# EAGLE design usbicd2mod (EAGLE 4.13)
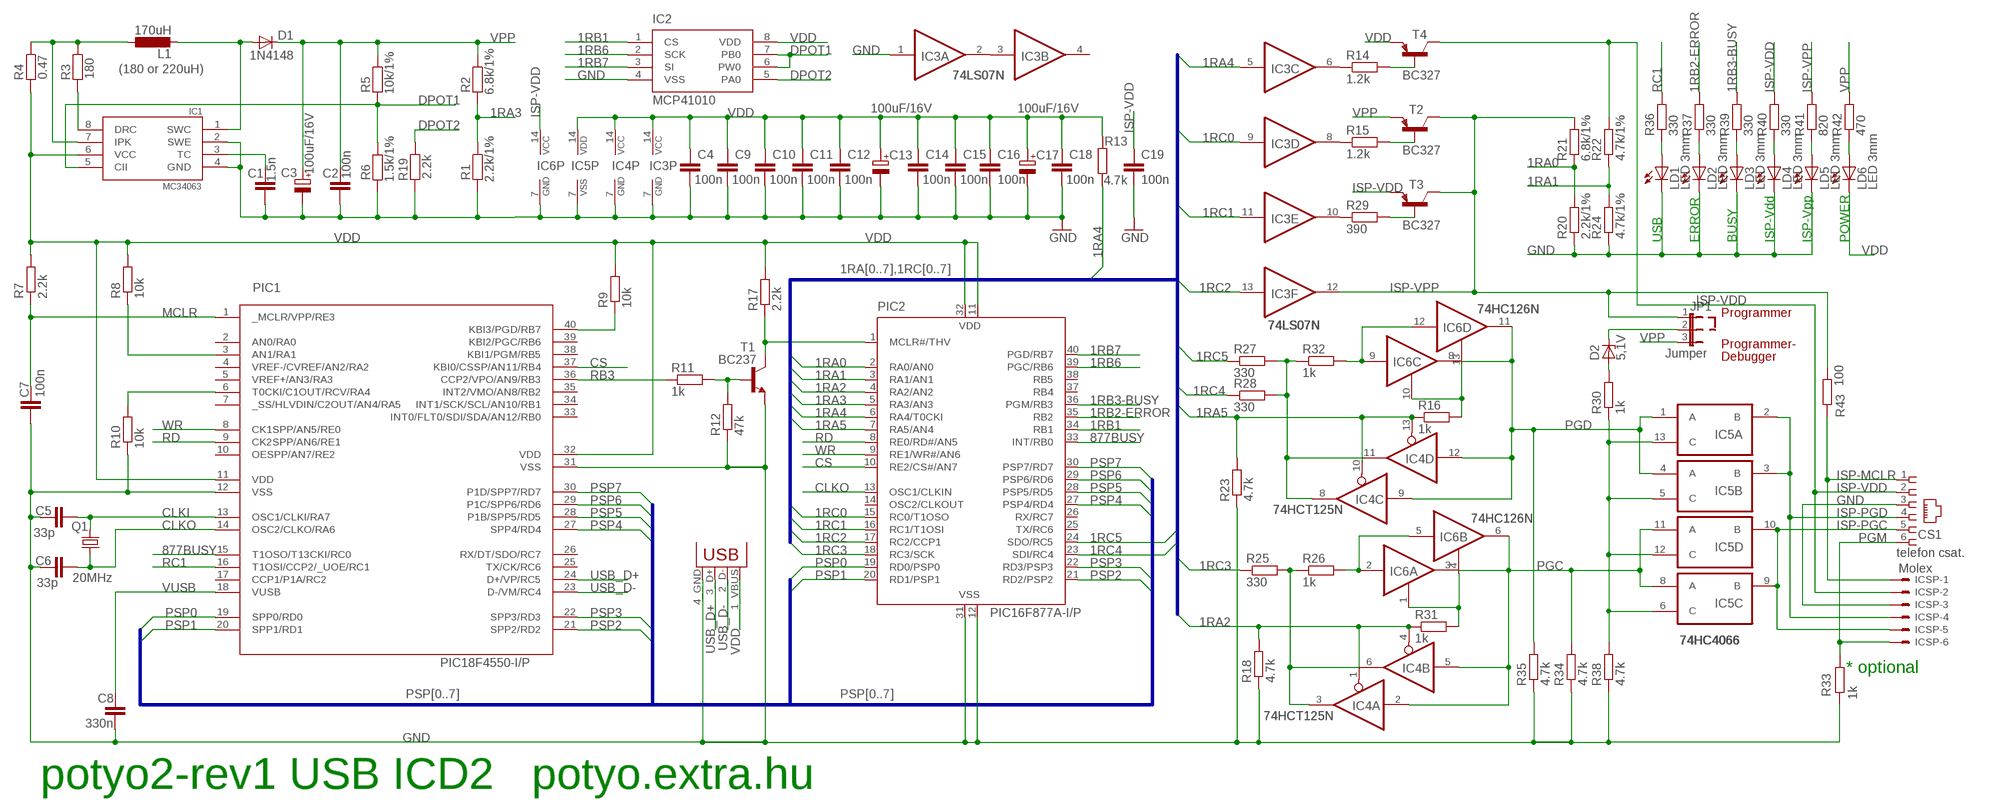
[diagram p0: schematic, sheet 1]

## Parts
C1  1.5n  C-EU025-025X050  [C025-025X050]
C2  100n  C-EU025-024X044  [C025-024X044]
C3  100uF/16V  CPOL-EUE2.5-5  [E2,5-5]
C4  100n  C-EU025-024X044  [C025-024X044]
C5  33p  C-EU025-024X044  [C025-024X044]
C6  33p  C-EU025-024X044  [C025-024X044]
C7  100n  C-EU025-024X044  [C025-024X044]
C8  330n  C-EU050-035X075  [C050-035X075]
C9  100n  C-EU025-024X044  [C025-024X044]
C10  100n  C-EU025-024X044  [C025-024X044]
C11  100n  C-EU025-024X044  [C025-024X044]
C12  100n  C-EU025-024X044  [C025-024X044]
C13  100uF/16V  CPOL-EUE2.5-5  [E2,5-5]
C14  100n  C-EU025-024X044  [C025-024X044]
C15  100n  C-EU025-024X044  [C025-024X044]
C16  100n  C-EU025-024X044  [C025-024X044]
C17  100uF/16V  CPOL-EUE2.5-5  [E2,5-5]
C18  100n  C-EU025-024X044  [C025-024X044]
C19  100n  C-EU025-024X044  [C025-024X044]
CS1  telefon csat.  520470-3  [520470-3]
D1  1N4148  1N414834-5  [DO34-5]
D2  5,1V  ZENER-DIODEDO34-5  [DO34Z5]
IC1  MC34063  MC34063-DIL  [DIL08]
IC2  MCP41010  [DIL8]
IC3  74LS07N  [DIL14]
IC4  74HCT125N  74HC125N  [DIL14]
IC5  74HC4066  4066N  [DIL14]
IC6  74HC126N  [DIL14]
ICSP  Molex  22-05-7068-06  [7395-06]
JP1  Jumper  JP2E  [JP2]
L1  170uH  L-EUL2207VM  [L2207VM]
LD1  LED 3mm  LED3MM  [LED3MM]
LD2  LED 3mm  LED3MM  [LED3MM]
LD3  LED 3mm  LED3MM  [LED3MM]
LD4  LED 3mm  LED3MM  [LED3MM]
LD5  LED 3mm  LED3MM  [LED3MM]
LD6  LED 3mm  LED3MM  [LED3MM]
PIC1  PIC18F4550-I/P  [DIL40]
PIC2  PIC16F877A-I/P  PIC16F877P  [DIL40]
Q1  20MHz  CRYTALHC49U-V  [HC49U-V]
R1  2.2k/1%  R-EU_0204/5  [0204/5@1]
R2  6.8k/1%  R-EU_0204/5  [0204/5@1]
R3  180  R-EU_0204/5  [0204/5@1]
R4  0.47  R-EU_0204/5  [0204/5@1]
R5  10k/1%  R-EU_0204/5  [0204/5@1]
R6  1.5k/1%  R-EU_0204/5  [0204/5@1]
R7  2.2k  R-EU_0204/5  [0204/5@1]
R8  10k  R-EU_0204/5  [0204/5@1]
R9  10k  R-EU_0204/5  [0204/5@1]
R10  10k  R-EU_0204/5  [0204/5@1]
R11  1k  R-EU_0204/5  [0204/5@1]
R12  47k  R-EU_0204/5  [0204/5@1]
R13  4.7k  R-EU_0204/5  [0204/5@1]
R14  1.2k  R-EU_0204/5  [0204/5@1]
R15  1.2k  R-EU_0204/5  [0204/5@1]
R16  1k  R-EU_0204/5  [0204/5@1]
R17  2.2k  R-EU_0204/5  [0204/5@1]
R18  4.7k  R-EU_0204/5  [0204/5@1]
R19  2.2k  R-EU_0204/5  [0204/5@1]
R20  2.2k/1%  R-EU_0204/5  [0204/5@1]
R21  6.8k/1%  R-EU_0204/5  [0204/5@1]
R22  4.7k/1%  R-EU_0204/5  [0204/5@1]
R23  4.7k  R-EU_0204/5  [0204/5@1]
R24  4.7k/1%  R-EU_0204/5  [0204/5@1]
R25  330  R-EU_0204/5  [0204/5@1]
R26  1k  R-EU_0204/5  [0204/5@1]
R27  330  R-EU_0204/5  [0204/5@1]
R28  330  R-EU_0204/5  [0204/5@1]
R29  390  R-EU_0204/5  [0204/5@1]
R30  1k  R-EU_0204/5  [0204/5@1]
R31  1k  R-EU_0204/5  [0204/5@1]
R32  1k  R-EU_0204/5  [0204/5@1]
R33  1k  R-EU_0204/5  [0204/5@1]
R34  4.7k  R-EU_0204/5  [0204/5@1]
R35  4.7k  R-EU_0204/5  [0204/5@1]
R36  330  R-EU_0204/5  [0204/5@1]
R37  330  R-EU_0204/5  [0204/5@1]
R38  4.7k  R-EU_0204/5  [0204/5@1]
R39  330  R-EU_0204/5  [0204/5@1]
R40  330  R-EU_0204/5  [0204/5@1]
R41  820  R-EU_0204/5  [0204/5@1]
R42  470  R-EU_0204/5  [0204/5@1]
R43  100  R-EU_0204/5  [0204/5@1]
T1  BC237  [TO92]
T2  BC327  [TO92]
T3  BC327  [TO92]
T4  BC327  [TO92]
USB  USB-B-H  [USB-B-H]

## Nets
1RA0: PIC2.2(RA0/AN0) R20.2 R21.1
1RA1: PIC2.3(RA1/AN1) R22.1 R24.2
1RA2: IC4.1(A:OE) IC4.4(B:OE) PIC2.4(RA2/AN2) R18.2 R31.1
1RA3: PIC2.5(RA3/AN3) R1.1 R2.2
1RA4: IC3.5(C:I) PIC2.6(RA4/T0CKI) R13.1
1RA5: IC4.10(C:OE) IC4.13(D:OE) PIC2.7(RA5/AN4) R16.1 R23.2
1RB1: IC2.1(CS) PIC2.34(RB1)
1RB2-ERROR: PIC2.35(RB2) R37.2
1RB3-BUSY: PIC2.36(PGM/RB3) R39.2
1RB6: IC2.2(SCK) PIC2.39(PGC/RB6)
1RB7: IC2.3(SI) PIC2.40(PGD/RB7)
1RC0: IC3.9(D:I) PIC2.15(RC0/T1OSO)
1RC1: IC3.11(E:I) PIC2.16(RC1/T1OSI)
1RC2: IC3.13(F:I) PIC2.17(RC2/CCP1)
1RC3: PIC2.18(RC3/SCK) R25.1
1RC4: PIC2.23(SDI/RC4) R28.1
1RC5: PIC2.24(SDO/RC5) R27.1
877BUSY: PIC1.15(T1OSO/T13CKI/RC0) PIC2.33(INT/RB0)
CLKI: C5.2 PIC1.13(OSC1/CLKI/RA7) Q1.2
CLKO: C6.2 PIC1.14(OSC2/CLKO/RA6) PIC2.13(OSC1/CLKIN) Q1.1
CMOS-EN: IC5.5(B:C) IC5.6(C:C) IC5.12(D:C) IC5.13(A:C) R30.1 R38.2
CS: PIC1.37(KBI0/CSSP/AN11/RB4) PIC2.10(RE2/CS#/AN7)
DPOT1: IC1.5(CII) IC2.6(PW0) IC2.7(PB0) R5.2 R6.2
DPOT2: IC2.5(PA0) R19.1
GND: C1.2 C2.2 C3.- C4.2 C5.1 C6.1 C7.2 C8.2 C9.2 C10.2 C11.2 C12.2 C13.- C14.2 C15.2 C16.2 C17.- C18.2 C19.2 CS1.3 IC1.2(SWE) IC1.4(GND) IC2.4(VSS) IC3.1(A:I) IC3.7(P:GND) IC4.7(P:GND) IC5.7(P:VSS) IC6.7(P:GND) ICSP.3 LD1.K(C) LD2.K(C) LD3.K(C) LD4.K(C) LD5.K(C) PIC1.12(VSS) PIC1.31(VSS) PIC2.12(VSS) PIC2.31(VSS) R1.2 R6.1 R10.1 R12.1 R18.1 R19.2 R20.1 R23.1 R24.1 R33.2 R34.1 R35.1 R38.1 T1.1(E) USB.4_GND(GND)
ISP-MCLR: CS1.1 ICSP.1 R43.1
ISP-PGC: CS1.5 IC5.9(C:B) IC5.10(D:B) ICSP.5
ISP-PGD: CS1.4 IC5.2(A:B) IC5.3(B:B) ICSP.4
ISP-VDD: C19.1 CS1.2 IC6.14(P:VCC) ICSP.2 R22.2 R40.2 T3.1(E) T4.3(C)
ISP-VPP: IC3.12(F:O) JP1.1 R21.2 R41.2 R43.2 T2.3(C) T3.3(C)
MCLR: C7.1 PIC1.1(_MCLR/VPP/RE3) R7.1
N$1: R11.2 R12.2 T1.2(B)
N$2: IC4.3(A:O) IC4.6(B:O) R25.2 R26.1
N$4: IC1.7(IPK) L1.1 R3.1 R4.1
N$5: PIC1.3(AN1/RA1) R8.1
N$6: LD6.A R42.1
N$7: D2.C JP1.2
N$8: C1.1 IC1.3(TC)
N$9: IC1.8(DRC) R3.2
N$10: IC6.2(A:I) IC6.5(B:I) R26.2
N$11: IC4.8(C:O) IC4.11(D:O) R27.2 R28.2 R32.1
N$12: IC3.2(A:O) IC3.3(B:I)
N$13: IC3.6(C:O) R14.1
N$14: D1.A IC1.1(SWC) L1.2
N$15: R14.2 T4.2(B)
N$16: PIC2.1(MCLR#/THV) R17.1 T1.3(C)
N$17: IC3.8(D:O) R15.1
N$18: R15.2 T2.2(B)
N$19: IC3.10(E:O) R29.1
N$20: R29.2 T3.2(B)
N$21: IC6.10(C:OE) IC6.13(D:OE) R16.2
N$22: IC6.1(A:OE) IC6.4(B:OE) R31.2
N$23: LD5.A R41.1
N$24: LD4.A R40.1
N$25: LD3.A R39.1
N$26: LD2.A R37.1
N$27: LD1.A R36.1
N$28: D2.A R30.2
N$29: IC6.9(C:I) IC6.12(D:I) R32.2
PGC: IC4.2(A:I) IC4.5(B:I) IC5.8(C:A) IC5.11(D:A) IC6.3(A:O) IC6.6(B:O) R34.2
PGD: IC4.9(C:I) IC4.12(D:I) IC5.1(A:A) IC5.4(B:A) IC6.8(C:O) IC6.11(D:O) R35.2
PGM: CS1.6 ICSP.6 R33.1
PSP0: PIC1.19(SPP0/RD0) PIC2.19(RD0/PSP0)
PSP1: PIC1.20(SPP1/RD1) PIC2.20(RD1/PSP1)
PSP2: PIC1.21(SPP2/RD2) PIC2.21(RD2/PSP2)
PSP3: PIC1.22(SPP3/RD3) PIC2.22(RD3/PSP3)
PSP4: PIC1.27(SPP4/RD4) PIC2.27(PSP4/RD4)
PSP5: PIC1.28(P1B/SPP5/RD5) PIC2.28(PSP5/RD5)
PSP6: PIC1.29(P1C/SPP6/RD6) PIC2.29(PSP6/RD6)
PSP7: PIC1.30(P1D/SPP7/RD7) PIC2.30(PSP7/RD7)
RA4: PIC1.6(T0CKI/C1OUT/RCV/RA4) R10.2
RB3: PIC1.36(CCP2/VPO/AN9/RB3) R11.1
RB7: PIC1.40(KBI3/PGD/RB7) R9.1
RC1: PIC1.16(T1OSI/CCP2/_UOE/RC1) R36.2
RD: PIC1.9(CK2SPP/AN6/RE1) PIC2.8(RE0/RD#/AN5)
USB_D+: PIC1.24(D+/VP/RC5) USB.3_D+(D+)
USB_D-: PIC1.23(D-/VM/RC4) USB.2_D-(D-)
VDD: C4.1 C9.1 C10.1 C11.1 C12.1 C13.+ C14.1 C15.1 C16.1 C17.+ C18.1 IC1.6(VCC) IC2.8(VDD) IC3.14(P:VCC) IC4.14(P:VCC) IC5.14(P:VDD) LD6.K(C) PIC1.11(VDD) PIC1.32(VDD) PIC2.11(VDD) PIC2.32(VDD) R4.2 R7.2 R8.2 R9.2 R13.2 R17.2 T4.1(E) USB.1_VBUS(VBUS)
VPP: C2.1 C3.+ D1.C JP1.3 R2.1 R5.1 R42.2 T2.1(E)
VUSB: C8.1 PIC1.18(VUSB)
WR: PIC1.8(CK1SPP/AN5/RE0) PIC2.9(RE1/WR#/AN6)
Unconnected: IC3.4(B:O) PIC1.2(AN0/RA0) PIC1.4(VREF-/CVREF/AN2/RA2) PIC1.5(VREF+/AN3/RA3) PIC1.7(_SS/HLVDIN/C2OUT/AN4/RA5) PIC1.10(OESPP/AN7/RE2) PIC1.17(CCP1/P1A/RC2) PIC1.25(TX/CK/RC6) PIC1.26(RX/DT/SDO/RC7) PIC1.33(INT0/FLT0/SDI/SDA/AN12/RB0) PIC1.34(INT1/SCK/SCL/AN10/RB1) PIC1.35(INT2/VMO/AN8/RB2) PIC1.38(KBI1/PGM/RB5) PIC1.39(KBI2/PGC/RB6) PIC2.14(OSC2/CLKOUT) PIC2.25(TX/RC6) PIC2.26(RX/RC7) PIC2.37(RB4) PIC2.38(RB5)

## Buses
PSP[0..7]
1RA[0..7],1RC[0..7]

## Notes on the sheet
- (180 or 220uH)
- USB | ERROR | BUSY | ISP-Vdd | ISP-Vpp | POWER
- Programmer
- Programmer-
- Debugger
- * optional
- potyo2-rev1 USB ICD2   potyo.extra.hu

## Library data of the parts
C1 C2 C4-C12 C14-C16 C18 C19 = rcl:C-EU: CAPACITOR, European symbol
C3 C13 C17 = rcl:CPOL-EU: POLARIZED CAPACITOR, European symbol
CS1 = con-amp:520470-3: AMP connector
D1 = diode:1N4148: DIODE
D2 = diode:ZENER-DIODE: Z-Diode
IC1 = mc34063:MC34063-DIL: DC/DC converter MC34063 in DIL08.
IC2 = microchip5:MCP41010
IC3 = 74xx-eu:74*07: Hex BUFFER, open collector high-voltage output
IC4 = 74xx-eu:74*125: Quad bus BUFFER, 3-state
IC5 = 40xx:4066: Quad bilateral ANALOG SWITCH
IC6 = 74xx-eu:74*126: Quad bus BUFFER, 3-state
ICSP = con-molex:22-?-06: CONNECTOR wire to board 2.54 mm (.1 inch) pitch header
JP1 = jumper:JP2E: JUMPER
L1 = rcl:L-EU: INDUCTOR, European symbol
LD1-LD6 = led:LED: LED
PIC1 = microchip-pic18fxx5x:PIC18*4550: PIC18*4550 Microchip FLASH Microcontroller with FS-USB DEVICE FEATURES FeaturePIC18*4550 Program Memory (bytes) 32k Program Memory (instructions) 16384 I/O Ports Ports A, B, C, D, E Capture/Compare/PWM Modules 1 Enhanced Capture/Compare/PWM Modules 1 Parallel Communications (PSP) Yes 10-bit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
PIC2 = microchip4:PIC16F87*: MICROCONTROLLER
Q1 = crystal:CRYTAL: CRYSTAL
R1-R43 = rcl:R-EU_: RESISTOR, European symbol
T1 = transistor-npn:BC237: NPN Transistor
T2-T4 = transistor-pnp:BC327: PNP Transistor
USB = con-usb:USB: USB Connectors

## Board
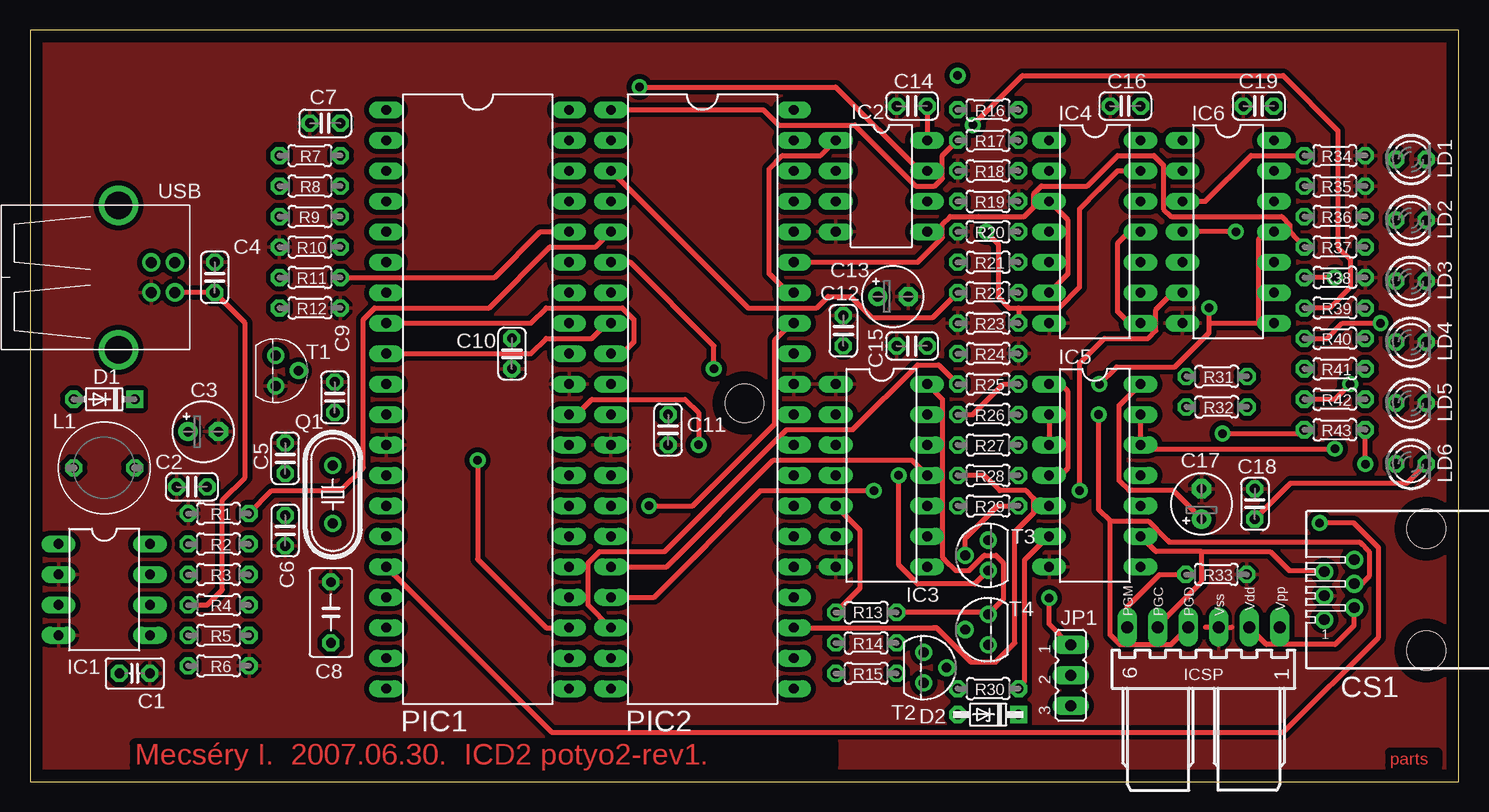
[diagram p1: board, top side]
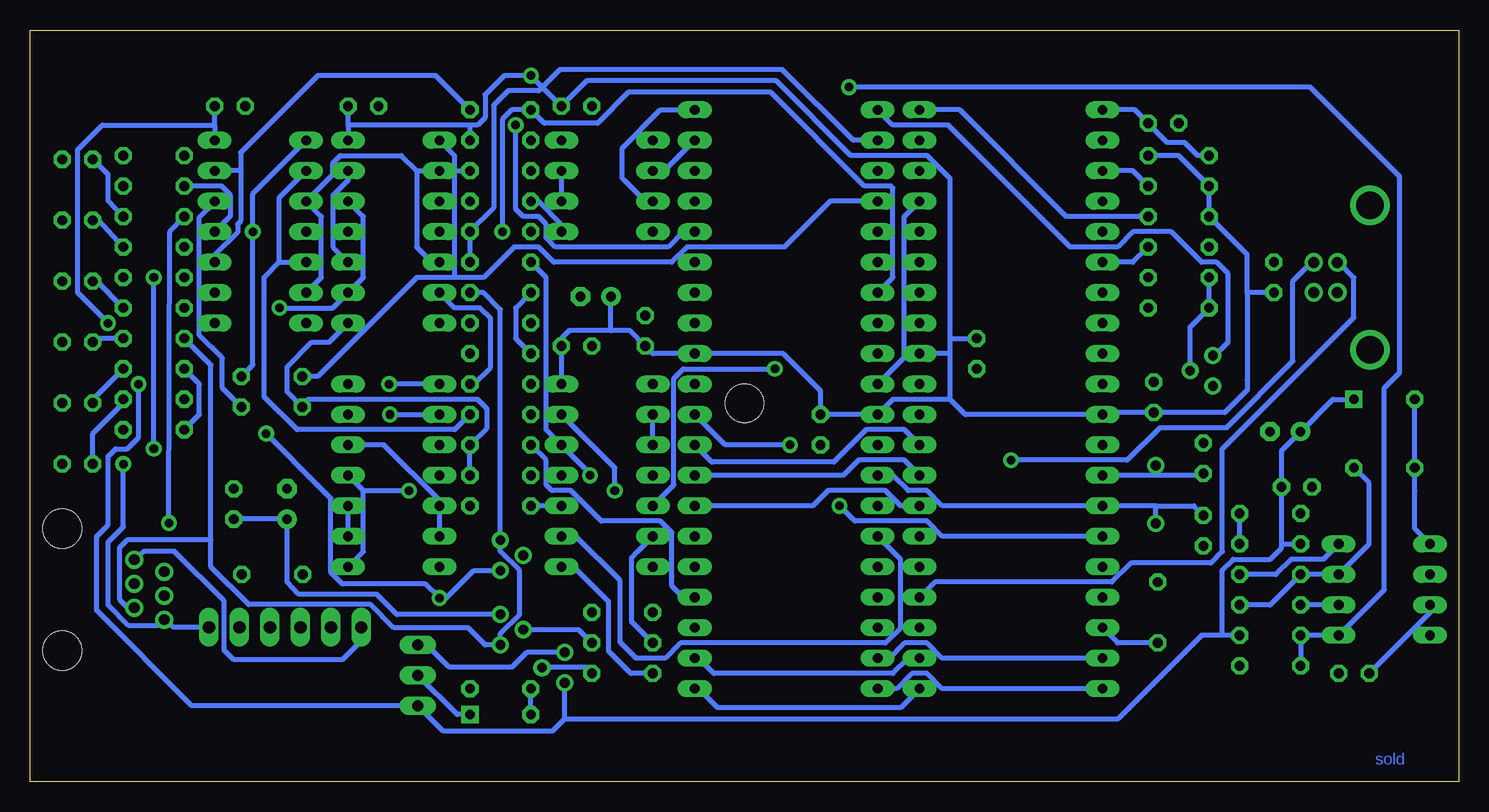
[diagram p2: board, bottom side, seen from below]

Size 119.05 x 62.7 mm. Coordinates in mm from the lower left corner, seen from the top.
Outline: 0,0 119.05,0 119.05,62.7 0,62.7 0,0
Copper layers (1*16): Top 0.035mm / dielectric 1.5mm / Bottom 0.035mm
Design rules "default": minimum track width 12mil, minimum drill 28mil, track to track 10mil, track to pad 10mil, pad to pad 10mil, via to via 10mil, smd to smd 10mil, copper to edge 40mil, drill to drill 8mil, minimum pad ring 12mil, minimum via ring 12mil, stop-mask expansion 4mil, vias tented up to drill 0mil, thermal gap 12mil
Holes 3.2 mm at 59.53,31.59

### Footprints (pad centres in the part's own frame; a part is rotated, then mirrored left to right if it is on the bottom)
C025-025X050 = drill 0.813 octagon: 1 -1.27,0; 2 1.27,0
C025-024X044 = drill 0.813 octagon: 1 -1.27,0; 2 1.27,0
E2,5-5 = drill 0.813 pad 1.6 round: + -1.27,0 | drill 0.813 pad 1.6 octagon: - 1.27,0
C050-035X075 = drill 0.813 octagon: 1 -2.54,0; 2 2.54,0
520470-3 = drill 0.889 round: 1 -2.5,8.5; 2 -1.5,6; 3 -0.5,8.5; 4 0.5,6; 5 1.5,8.5; 6 2.5,6 | hole 3.251: -5.08,0; 5.08,0
DO34-5 = drill 0.813 octagon: A 2.54,0 | drill 0.813 square: C -2.54,0
DO34Z5 = drill 0.813 pad 1.422 octagon: A 2.54,0 | drill 0.813 pad 1.422 square: C -2.54,0
DIL08 = drill 0.813 long: 1 -3.81,-3.81; 2 -1.27,-3.81; 3 1.27,-3.81; 4 3.81,-3.81; 5 3.81,3.81; 6 1.27,3.81; 7 -1.27,3.81; 8 -3.81,3.81
DIL8 = drill 0.813 long: 1 -3.81,-3.81; 2 -1.27,-3.81; 3 1.27,-3.81; 4 3.81,-3.81; 5 3.81,3.81; 6 1.27,3.81; 7 -1.27,3.81; 8 -3.81,3.81
DIL14 = drill 0.813 long: 1 -7.62,-3.81; 2 -5.08,-3.81; 3 -2.54,-3.81; 4 0,-3.81; 5 2.54,-3.81; 6 5.08,-3.81; 7 7.62,-3.81; 8 7.62,3.81; 9 5.08,3.81; 10 2.54,3.81; 11 0,3.81; 12 -2.54,3.81; 13 -5.08,3.81; 14 -7.62,3.81
7395-06 = drill 1.016 long: 1 6.35,0; 2 3.81,0; 3 1.27,0; 4 -1.27,0; 5 -3.81,0; 6 -6.35,0
JP2 = drill 0.914 long: 1 -2.54,0; 2 0,0; 3 2.54,0
L2207VM = drill 0.813 octagon: 1 -2.54,0; 2 2.54,0
LED3MM = drill 0.813 octagon: A -1.27,0; K 1.27,0
DIL40 = drill 0.813 long: 1 -24.13,-7.62; 2 -21.59,-7.62; 3 -19.05,-7.62; 4 -16.51,-7.62; 5 -13.97,-7.62; 6 -11.43,-7.62; 7 -8.89,-7.62; 8 -6.35,-7.62; 9 -3.81,-7.62; 10 -1.27,-7.62; 11 1.27,-7.62; 12 3.81,-7.62; 13 6.35,-7.62; 14 8.89,-7.62; 15 11.43,-7.62; 16 13.97,-7.62; 17 16.51,-7.62; 18 19.05,-7.62; 19 21.59,-7.62; 20 24.13,-7.62; 21 24.13,7.62; 22 21.59,7.62; 23 19.05,7.62; 24 16.51,7.62; 25 13.97,7.62; 26 11.43,7.62; 27 8.89,7.62; 28 6.35,7.62; 29 3.81,7.62; 30 1.27,7.62; 31 -1.27,7.62; 32 -3.81,7.62; 33 -6.35,7.62; 34 -8.89,7.62; 35 -11.43,7.62; 36 -13.97,7.62; 37 -16.51,7.62; 38 -19.05,7.62; 39 -21.59,7.62; 40 -24.13,7.62
HC49U-V = drill 0.813 round: 1 -2.413,0; 2 2.413,0
0204/5@1 = drill 0.813 octagon: 1 -2.54,0; 2 2.54,0
TO92 = drill 0.813 round: 1 1.27,0; 2 0,1.905; 3 -1.27,0
USB-B-H = drill 0.914 round: 1_VBUS 14.465,-1.25; 2_D- 14.465,1.25; 3_D+ 12.484,1.25; 4_GND 12.484,-1.25 | drill 2.286 round: P$1 9.766,-6.02; P$2 9.766,6.02

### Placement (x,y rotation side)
C1  8.73,9.04 0 top
C2  13.49,24.6 180 top
C3  14.44,29.21 0 top
C4  15.39,42.06 90 top
C5  21.27,26.98 270 top
C6  21.27,20.95 90 top
C7  24.6,54.92 180 top
C8  25.08,14.12 90 top
C9  25.39,32.06 90 top
C10  40.16,35.71 270 top
C11  53.18,29.36 270 top
C12  67.78,37.62 90 top
C13  71.91,40.48 0 top
C14  73.5,56.35 180 top
C15  73.5,36.35 180 top
C16  91.28,56.35 180 top
C17  97.63,23.17 90 top
C18  102.07,23.17 90 top
C19  102.39,56.35 180 top
CS1  116.36,16.03 90 top
D1  6.19,31.9 180 top
D2  79.84,5.61 180 top
IC1  6.19,16.03 270 top
IC2  70.95,49.68 270 top
IC3  70.96,25.55 270 top
IC4  88.74,45.87 270 top
IC5  88.74,25.55 270 top
IC6  99.85,45.87 270 top
ICSP  97.78,12.89 0 top
JP1  86.73,8.89 270 top
L1  6.19,26.19 180 top
LD1  115.09,51.91 0 top
LD2  115.09,46.83 0 top
LD3  115.09,41.75 0 top
LD4  115.09,36.67 0 top
LD5  115.09,31.59 0 top
LD6  115.09,26.51 0 top
PIC1  37.3,31.9 270 top
PIC2  56.03,31.9 270 top
Q1  25.24,23.97 90 top
R1  15.71,22.38 180 top
R2  15.71,19.84 0 top
R3  15.71,17.3 0 top
R4  15.71,14.76 180 top
R5  15.71,12.22 180 top
R6  15.71,9.68 180 top
R7  23.33,52.22 0 top
R8  23.33,49.68 180 top
R9  23.33,47.14 180 top
R10  23.33,44.6 0 top
R11  23.33,42.06 180 top
R12  23.33,39.52 180 top
R13  69.69,14.12 0 top
R14  69.69,11.58 0 top
R15  69.69,9.04 0 top
R16  79.85,56.03 0 top
R17  79.84,53.49 0 top
R18  79.85,50.95 0 top
R19  79.85,48.41 0 top
R20  79.85,45.87 0 top
R21  79.85,43.33 180 top
R22  79.85,40.79 0 top
R23  79.85,38.25 0 top
R24  79.85,35.71 180 top
R25  79.85,33.17 0 top
R26  79.85,30.63 0 top
R27  79.85,28.09 0 top
R28  79.85,25.55 0 top
R29  79.85,23.01 0 top
R30  79.84,7.77 180 top
R31  98.9,33.81 0 top
R32  98.9,31.27 0 top
R33  98.86,17.3 0 top
R34  108.74,52.22 180 top
R35  108.74,49.68 180 top
R36  108.74,47.14 180 top
R37  108.74,44.6 180 top
R38  108.74,42.06 180 top
R39  108.74,39.52 180 top
R40  108.74,36.98 180 top
R41  108.74,34.44 180 top
R42  108.74,31.9 180 top
R43  108.74,29.36 180 top
T1  20.47,34.29 270 top
T2  74.48,9.52 270 top
T3  79.85,18.89 90 top
T4  79.85,12.7 90 top
USB  -2.39,42.06 0 top

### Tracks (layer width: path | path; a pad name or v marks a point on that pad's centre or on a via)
1RA0
  Bottom 0.406: PIC2.2 50.44,53.49 56.35,59.4 74.89,59.4 76.67,57.62 79.21,57.62 80.42,56.42 80.42,47.84 R20.2 82.39,43.27 | 82.39,43.27 R21.1 | 82.39,43.27
1RA1
  Top 0.406: PIC2.3 | PIC2.3 59.84,39.52 65.56,39.52 66.51,40.48 68.42,40.48 70.16,38.73 75.24,38.73 R22.1 | R22.1
  Bottom 0.406: R24.2 78.58,36.98 78.58,39.52 R22.1 77.46,40.79
1RA2
  Bottom 0.406: PIC2.4 52.38,48.41 56.19,44.6 64.29,44.6 65.56,43.33 75.4,43.33 76.67,44.6 78.7,44.6 81.24,42.06 83.66,42.06 | 83.66,45.87 IC4.4 | 83.66,42.06 83.66,45.87 | 83.66,45.87 83.66,50.95 | 83.66,50.95 83.66,52.22 IC4.1 | 83.66,50.95 R18.2 | 83.66,42.06 86.83,42.06 95.09,33.81 R31.1
1RA3
  Top 0.406: PIC2.5 47.14,44.6 43.33,44.6 38.25,39.52 28.73,39.52 27.78,38.57 27.78,26.19 25.87,24.28 20.16,24.28 R1.1
  Bottom 0.406: R2.2 R1.1
1RA4  (via drill 0.71)
  Top 0.406: PIC2.6 50,43.33 56.98,36.35 v56.98,34.44 v56.99,34.44 | R13.1 69.18,16.16 69.18,20.98 IC3.5
  Bottom 0.406: v56.99,34.44 64.61,34.44 65.4,33.65 65.4,24.76 IC3.5
1RA5  (via drill 0.71)
  Top 0.406: IC4.13 90.64,50.95 89.05,49.37 | 89.05,49.37 | 89.05,49.37 87.47,47.78 87.47,41.24 85.75,39.52 82.39,39.52 | 82.39,39.52 81.56,39.52 80.67,40.41 80.67,44.86 79.65,45.87 v79.69,45.87 | 82.39,39.52 R23.2 | 82.39,39.52
  Bottom 0.406: IC4.10 93.82,44.6 93.82,48.89 92.55,50.16 IC4.13 | v79.69,45.87 79.69,55.24 78.89,56.03 R16.1 76.19,54.92 71.75,54.92 69.18,57.49 | PIC2.7 47.14,42.06 47.14,49.53 | 47.14,49.53 | 47.14,49.53 47.3,49.68 49.52,49.68 57.33,57.49 69.18,57.49 | 69.18,57.49
1RB1
  Top 0.406: PIC2.34 63.18,40.79 61.59,42.38 61.59,51.11 62.7,52.22 65.87,52.22 IC2.1
1RB2-ERROR
  Top 0.406: R37.2 104.99,45.87 104.99,46.45 104.29,47.14 95.09,47.14 94.45,47.78 94.45,51.43 93.66,52.22 90.64,52.22 88.1,49.68 84.29,49.68 83.66,49.05 83.66,47.94 82.86,47.14 79.05,47.14 | 79.05,47.14 | 79.05,47.14 76.67,47.14 76.04,46.51 76.04,45.4 75.88,45.24 | PIC2.35 73.97,43.33 75.88,45.24 | 75.88,45.24
1RB3-BUSY  (via drill 0.71)
  Top 0.406: v78.58,54.76 82.7,58.89 104.42,58.89 | 104.42,58.89 104.45,58.89 | 110.01,41.24 | 110.01,41.24 108.29,39.52 R39.2 | R39.2 | 110.01,41.24 110.01,43.59 108.99,44.6 108.99,54.32 104.42,58.89
  Bottom 0.406: PIC2.36 64.61,45.87 65.88,44.6 75.27,44.6 76.03,45.37 76.03,46.51 76.67,47.14 77.94,47.14 78.58,47.78 v78.58,54.76
1RB6
  Bottom 0.406: PIC2.39 66.19,50.95 IC2.2
1RB7
  Bottom 0.406: PIC2.40 66.51,56.03 69.69,52.86 69.69,50.32 69.53,50.16 | 69.53,50.16 67.78,48.41 IC2.3 | 69.53,50.16
1RC0
  Bottom 0.406: PIC2.15 46.51,18.57 46.51,12.85 47.78,11.58 64.86,11.58 66.13,10.31 68.54,10.31 69.88,11.65 69.88,16.79 73.56,20.47 IC3.9
1RC1
  Top 0.406: IC3.11 73.5,26.82 61.94,26.82 53.05,17.93 PIC2.16
1RC2  (via drill 0.71)
  Top 0.406: PIC2.17 52,15.39 60.89,24.28 v70.32,24.28
  Bottom 0.406: IC3.13 70.32,26.19 v70.32,24.28
1RC3
  Top 0.406: R25.1 75.72,34.76 73.97,34.76 68.57,29.36 63.05,29.36 52.89,19.2 47.46,19.2 46.51,18.25 46.51,14.76 PIC2.18
1RC4
  Top 0.406: R28.1 79.53,25.55 80.8,24.28 83.02,24.28 83.66,23.65 83.65,23.65 83.65,22.44 82.07,20.86 82.07,11.58 80.48,10 78.42,10 75.56,12.85 75.24,12.85 | PIC2.23 75.24,12.85 | 75.24,12.85 75.4,12.85
1RC5
  Bottom 0.406: R27.1 76.04,26.82 76.04,24.76 75.56,24.28 73.97,24.28 71.43,21.74 66.51,21.74 65.56,20.79 | PIC2.24 64.61,15.39 65.56,16.35 65.56,17.14 | 65.56,17.14 | 65.56,20.79 | 65.56,17.14 65.56,20.79
877BUSY  (via drill 0.71)
  Top 0.406: PIC2.33 63.49,38.25 62.07,36.83 62.07,29.84 55.24,23.01 v51.59,23.01 | v51.59,23.01
  Bottom 0.406: v51.59,23.01 50.32,21.74 44.29,21.74 43.02,20.47 PIC1.15
CLKI
  Bottom 0.406: 25.24,25.55 PIC1.13 | 25.24,25.55 Q1.2 | 25.24,25.55 21.43,25.55 C5.2
CLKO
  Bottom 0.406: 25.24,23.01 PIC1.14 43.02,23.01 44.29,24.28 45.87,24.28 47.14,25.55 PIC2.13 | Q1.1 25.24,23.01 | C6.2 21.58,22.54 22.06,23.01 25.24,23.01
CMOS-EN  (via drill 0.71)
  Top 0.406: IC5.13 IC5.12 92.86,27.78 v108.74,27.78 | v108.74,42.06 R38.2 | IC5.6 84.93,20.54 84.92,20.54 82.89,18.51 82.89,8.35 R30.1
  Bottom 0.406: IC5.6 IC5.5 84.93,23.46 84.92,23.46 89.56,28.09 IC5.12 | v108.74,27.78 v108.74,42.06
CS
  Bottom 0.406: PIC2.10 46.19,35.4 46.19,47.14 PIC1.37
DPOT1  (via drill 0.71)
  Top 0.406: v50.79,57.94 67.15,57.94 74.13,50.95 IC2.7
  Bottom 0.406: R6.2 R5.2 IC1.5 | IC1.5 6.19,16.03 6.19,32.86 4.92,34.13 4.92,50.48 12.38,57.94 v50.79,57.94 | IC1.5 9.84,12.22 | IC2.7 IC2.6
DPOT2
  Bottom 0.406: IC2.5 74.76,46.51 76.67,48.41 R19.1
GND
  Top 0.406: 99.05,11.46 99.05,11.52 ICSP.3 | ICSP.3 100.17,12.89 | ICSP.3 97.94,12.89
  pour Top (isolate 0.406): -0.48,63.02 119.06,63.02 119.06,-0.32 -0.48,-0.32
ISP-MCLR  (via drill 0.71)
  Top 0.406: v111.28,26.51 R43.1
  Bottom 0.406: v111.28,26.51 111.28,21.27 112.55,20 112.55,14.76 110.8,13.01 108.42,13.01 107.9,13.53 CS1.1 107.13,12.89 ICSP.1
ISP-PGC
  Top 0.406: IC5.9 93.82,19.2 97.63,19.2 | CS1.5 107.86,17.54 107.79,17.62 104.93,17.62 103.34,19.2 97.63,19.2 | ICSP.5 | 97.63,19.2 97.63,16.66 97.62,16.66 93.97,13.01 ICSP.5
  Bottom 0.406: IC5.9 IC5.10
ISP-PGD  (via drill 0.71)
  Top 0.406: IC5.2 IC5.3 | 110.48,16.51 110.46,16.53 CS1.4 110.62,16.53 110.64,16.51 110.96,16.51 111.6,17.14 111.6,19.2 111.44,19.36 | 111.44,19.36 | 110.96,19.84 111.44,19.36 | 94.61,20.32 93.18,21.74 90.01,21.74 | 94.61,20.32 | 94.61,20.32 94.77,20.16 | 94.77,20.16 | 94.77,20.16 94.93,20 110.8,20 110.96,19.84 | 110.96,19.84 | 90.01,21.74 90,21.74 89.05,22.7 v89.05,30.63 | 90.01,21.74 90.01,12.25 90.8,11.46 95.09,11.46 ICSP.4
  Bottom 0.406: v89.05,30.63 IC5.2
ISP-VDD  (via drill 0.71)
  Top 0.406: v112.55,38.25 109.37,38.25 108.1,36.98 R40.2 | ICSP.2 103.02,11.46 108.77,11.46 110.33,13.01 110.33,14.53 CS1.2
  Bottom 0.406: 103.66,54.76 IC6.14 | 103.66,54.76 C19.1 | R40.2 103.98,34.76 103.98,20.16 | T3.1 | T3.1 79.85,19.2 78.26,17.62 78.26,13.97 79.85,12.38 T4.3 81.12,11.43 82.54,12.85 88.74,12.85 90.67,14.79 100.83,14.79 103.98,17.93 103.98,20.16 | 103.66,54.76 113.02,54.76 115.09,52.7 115.09,40.79 v112.55,38.25 | 103.98,20.16 110.96,20.16 111.59,19.52 111.6,19.52 111.6,15.24 110.89,14.53 110.33,14.53 | 110.33,14.53 CS1.2 | 110.33,14.53 110.33,14.44 | T3.1 79.85,39.4 81.24,40.79 R22.2
ISP-VPP  (via drill 0.71)
  Top 0.406: R43.2 106.36,29.36 106.04,29.05 v99.37,29.05 | v72.38,25.55 72.38,18.09 73.97,16.51 78.73,16.51 T3.3 | T3.3 | v84.92,15.33 84.92,13.17 86.7,11.39 JP1.1 | JP1.1
  Bottom 0.406: R43.2 104.93,30.63 104.93,33.17 R41.2 | T3.3 | v72.38,25.55 72.38,25.71 IC3.12 76.04,29.36 76.04,42.06 R21.2 | T3.3 82.07,17.62 84.35,15.33 v84.92,15.33 86.1,16.51 93.02,16.51 93.97,17.46 93.97,23.65 94.77,24.44 | 94.77,24.44 v99.37,29.05 | 94.77,24.44 | T2.3 77.65,10.79 78.89,9.55 84.1,9.55 85.94,11.39 86.7,11.39 JP1.1 | JP1.1 | R21.2
MCLR
  Bottom 0.406: PIC1.1 26.98,56.03 C7.1 25.87,54.89 24.28,53.3 22.82,53.3 21.74,52.22 R7.1
N$1
  Bottom 0.406: R12.2 R11.2 | R12.2 | T1.2 | T1.2 22.38,37.94 R12.2
N$2
  Top 0.406: R26.1 78.58,30.63 81.12,33.17 R25.2 | IC4.3 86.51,46.83 86.51,42.38 IC4.6
  Bottom 0.406: IC4.6 83.65,39.52 81.56,39.52 80.67,38.64 80.67,34.57 82.07,33.17 R25.2
N$4
  Bottom 0.406: R4.1 15.71,14.76 R3.1 IC1.7 7.46,19.84 7.46,24.92 7.45,24.92 L1.1 | L1.1
N$5
  Bottom 0.406: PIC1.3 27.14,50.95 R8.1 | R8.1
N$6
  Bottom 0.406: R42.1 111.28,31.59 113.82,29.05 LD6.A
N$7
  Bottom 0.406: D2.C 83.46,5.61 JP1.2 | JP1.2 | JP1.2 | JP1.2 | JP1.2 86.7,8.92
N$8
  Bottom 0.406: C1.1 2.38,14.12 IC1.3
N$9
  Bottom 0.406: IC1.8 11.27,18.57 13.96,18.57 15.23,17.3 R3.2
N$10
  Bottom 0.406: 98.26,43.33 IC6.5 | IC6.2 98.26,48.73 98.26,43.33 | 98.26,43.33 99.53,42.06 99.53,32.09 96.8,29.36 83.66,29.36 R26.2
N$11
  Top 0.406: IC4.11 91.59,45.87 90.64,44.92 90.64,39.21 91.59,38.25 IC4.8
  Bottom 0.406: IC4.8 94.13,36.67 95.56,36.67 97.63,34.6 97.63,32.54 R32.1 96.51,31.27 95.88,31.9 81.75,31.9 80.96,31.11 80.96,29.52 R27.2 R28.2
N$12
  Bottom 0.406: IC3.3 IC3.2
N$13
  Bottom 0.406: IC3.6 68.42,19.2 68.92,18.7 68.92,13.36 R14.1
N$14
  Bottom 0.406: L1.2 D1.A | 3.65,24.28 L1.2 | 3.65,24.28 3.65,21.11 IC1.1 | 3.65,24.28 | L1.2 | L1.2
N$15
  Bottom 0.406: R14.2 | T4.2 73.34,12.7 R14.2
N$16
  Top 0.406: R17.1 | PIC2.1 61.11,56.03 62.38,54.76 68.73,54.76 73.81,49.68 75.4,49.68 76.03,50.32 76.03,52.22 R17.1
  Bottom 0.406: PIC2.1 | PIC2.1 47.14,54.76 42.54,54.76 32.54,44.76 | 32.54,44.76 | 32.54,44.76 32.38,44.6 28.41,44.6 27.14,45.87 23.97,45.87 23.33,45.24 | 23.33,45.24 | 23.33,45.24 21.43,43.33 20.16,43.33 19.2,42.38 19.2,36.67 | 19.2,36.67 | 19.2,36.67 20.31,35.56 T1.3 | R17.1
N$17
  Bottom 0.406: R15.1 68.99,9.04 70.83,10.89 70.83,15.01 73.75,17.93 IC3.8
N$18
  Bottom 0.406: R15.2 72.73,9.55 76.35,9.55 T2.2
N$19
  Bottom 0.406: IC3.10 R29.1
N$20
  Top 0.406: T3.2 77.94,20.32 80.64,23.01 R29.2
N$21
  Bottom 0.406: R16.2 85.24,58.89 95.09,58.89 101.5,52.48 | IC6.10 103.66,43.91 101.75,45.81 101.75,46.51 101.5,46.76 101.5,50.89 | 101.5,52.48 | 101.5,52.48 101.5,50.89 | IC6.13 101.56,50.95 101.5,50.89
N$22  (via drill 0.71)
  Top 0.406: v100.48,45.87 IC6.4
  Bottom 0.406: R31.2 100.48,34.76 v100.48,45.87 100.48,49.05 IC6.1
N$23
  Bottom 0.406: R41.1 113.82,31.9 LD5.A
N$24
  Bottom 0.406: R40.1 113.82,36.98 LD4.A
N$25
  Bottom 0.406: LD3.A 113.5,41.75 R39.1
N$26
  Bottom 0.406: R37.1 113.31,46.83 LD2.A
N$27
  Bottom 0.406: R36.1 112.55,48.48 112.55,50.64 LD1.A
N$28
  Bottom 0.406: D2.A R30.2
N$29
  Bottom 0.406: R32.2 103.02,32.86 103.02,35.33 104.93,37.24 104.93,40.79 | 103.66,48.35 | 103.66,48.35 IC6.12 | 104.93,40.79 104.93,47.08 103.66,48.35 | 104.93,40.79 IC6.9
PGC  (via drill 0.71)
  Top 0.406: R34.2 101.75,52.22 97.94,48.41 IC6.3 | v87.47,24.28 87.47,34.92 89.53,36.98 93.18,36.98 93.82,37.62 93.82,39.37 95.24,40.79 IC6.6
  Bottom 0.406: IC5.8 91.28,19.2 91.28,24.28 | 91.28,24.28 IC5.11 | 91.28,24.28 v87.47,24.28 | 86.83,50.95 88.1,52.22 93.18,52.22 93.82,51.59 93.82,50.64 IC6.3 94.77,47.14 94.77,42.06 IC6.6 | 86.83,50.95 IC4.2 | IC4.5 85.56,43.33 86.83,44.6 86.83,50.95
PGD  (via drill 0.71)
  Top 0.406: IC5.4 85.88,25.55 86.51,26.19 86.51,32.54 85.88,33.17 IC5.1 | 102.39,38.25 IC6.8 | IC6.11 103.02,45.87 102.39,45.24 102.39,38.25 | 98.26,38.25 v98.26,39.52 | 98.26,38.25 102.39,38.25 | v89.12,33.17 90.54,34.6 95.4,34.6 98.26,37.46 98.26,38.25
  Bottom 0.406: IC4.12 91.28,47.14 91.28,42.06 IC4.9 93.82,39.52 v98.26,39.52 | IC5.1 v89.12,33.17 | R35.2 103.09,49.68 102.32,48.92 102.32,47.21 IC6.11 | IC6.11
PGM
  Top 0.406: ICSP.6 91.43,14.6 94.13,17.3 R33.1
  Bottom 0.406: ICSP.6 91.43,11.77 93.02,10.19 102.07,10.19 102.86,10.98 102.86,15.08 107.02,19.24 109.53,19.24 110.33,18.57 110.33,18.53 CS1.6
PSP0
  Bottom 0.406: PIC1.19 43.02,10.31 44.29,11.58 46.19,11.58 47.46,10.31 PIC2.19
PSP1
  Bottom 0.406: PIC1.20 43.02,7.77 44.29,9.04 45.56,9.04 46.83,7.77 PIC2.20
PSP2
  Bottom 0.406: PIC2.21 63.34,7.77 61.75,6.19 46.51,6.19 PIC1.21
PSP3
  Bottom 0.406: PIC2.22 63.34,10.31 62.07,9.04 47.14,9.04 45.87,10.31 PIC1.22
PSP4
  Bottom 0.406: PIC1.27 46.51,23.01 47.78,24.28 52.54,24.28 53.81,23.01 PIC2.27
PSP5
  Bottom 0.406: PIC1.28 46.19,26.82 50,26.82 51.27,25.55 PIC2.28
PSP6
  Bottom 0.406: PIC1.29 46.19,29.36 49.37,29.36 52.06,26.67 62.22,26.67 PIC2.29 | PIC2.29
PSP7  (via drill 0.71)
  Top 0.406: PIC1.30 45.56,30.63 46.83,31.9 54.6,31.9 55.72,30.79 v55.72,28.09
  Bottom 0.406: PIC2.30 | PIC2.30 61.11,28.09 v55.72,28.09
RA4
  Bottom 0.406: R10.2 27.14,43.33 PIC1.6
RB3
  Top 0.406: PIC1.36 42.54,45.87 38.73,42.06 R11.1
RB7
  Bottom 0.406: R9.1 32.7,47.14 41.59,56.03 PIC1.40
RC1  (via drill 0.71)
  Top 0.406: PIC1.16 43.49,4.12 104.45,4.12 112.39,12.06 112.39,19.52 110.33,21.59 v107.47,21.59
  Bottom 0.406: v107.47,21.59 107.4,45.87 R36.2
RD
  Top 0.406: PIC1.9 41.75,35.71 43.02,36.98 46.83,36.98 48.1,38.25 PIC2.8
USB_D+
  Bottom 0.406: USB.3_D+ 10.02,43.31 10,43.33 8.73,42.06 8.73,38.73 19.68,27.78 19.68,19.2 20.63,18.25 27.3,18.25 28.89,16.66 43.65,16.66 PIC1.24
USB_D-  (via drill 0.71)
  Top 0.406: v37.3,26.82 37.3,18.57 43.02,12.85 PIC1.23
  Bottom 0.406: USB.2_D- 12.2,43.31 12.22,43.33 13.81,41.75 13.81,35.08 19.36,29.52 24.92,29.52 27.62,26.82 v37.3,26.82
VDD  (via drill 0.71)
  Top 0.406: LD6.K 114.77,24.92 105.05,24.92 102.07,21.93 C18.1 | T4.1 81.12,15.24 81.12,18.25 80.48,18.89 79.53,18.89 78.26,17.62 77.15,17.62 76.19,18.57 76.04,18.73 76.04,31.9 IC3.14 | 17.93,38.25 17.93,25.4 16.03,23.49 16.03,16.03 14.76,14.76 R4.2 | T4.1 79.85,13.93 79.84,13.93 79.78,14 | IC2.8 74.76,56.42 74.77,56.41 C14.1 | 79.78,14 79.81,13.97 T4.1 | R13.2 79.65,14.12 79.78,14 | IC5.14 90.77,31.4 90.77,25.11 91.59,24.28 95.28,24.28 97.63,21.93 C17.+ | USB.1_VBUS 12.09,40.79 C4.1 | C4.1 | 17.93,38.25 | 17.93,38.25 C4.1 | IC3.14
  Bottom 0.406: v77.31,58.89 79.53,58.89 81.12,57.3 81.12,55.4 81.75,54.76 82.39,54.76 | R9.2 R8.2 23.33,52.22 R7.2 | 42.38,35.71 PIC1.32 | 42.38,35.71 42.38,36.98 | 42.38,36.98 42.38,50.32 44.29,52.22 50.64,52.22 56.86,58.45 72.67,58.45 C14.1 | PIC2.11 47.14,31.9 42.38,31.9 | 42.38,31.9 42.38,35.71 | PIC1.11 41.11,30.63 42.38,31.9 | R7.2 | IC1.6 R4.2 | 82.39,54.76 92.54,54.76 | R17.2 | 82.39,54.76 R17.2 | 67.14,35.71 PIC2.32 56.29,35.71 53.18,32.6 C11.1 PIC2.11 | T4.1 88.48,13.97 90.16,15.65 96.64,15.65 97.63,16.7 97.63,16.73 | 17.62,40.79 17.62,33.49 17.61,33.49 17.61,32.67 19.49,30.79 C9.1 29.52,30.79 PIC1.11 | 17.62,40.79 17.62,43.97 17.61,43.97 R9.2 | R9.2 | PIC2.11 48.48,30.63 48.54,30.57 48.6,30.63 | 92.54,54.76 92.55,54.76 92.55,54.7 | 92.54,54.76 92.55,54.76 | 70.64,37.62 74.13,37.62 74.77,36.98 C15.1 74.77,36.29 | 70.64,37.62 C13.+ | 42.38,36.98 C10.1 | C14.1 | v77.31,58.89 | C14.1 v77.31,58.89 | 92.55,54.7 92.54,54.7 | 92.55,54.7 C16.1 | 92.54,54.7 92.55,54.7 | 92.55,54.7 IC4.14 | 92.54,54.7 92.55,54.7 | 17.61,40.79 17.62,40.79 | 17.61,40.79 | C4.1 17.61,40.79 | PIC1.11 | 97.63,16.73 97.62,16.73 | 97.62,16.73 97.63,16.73 | 102.07,21.93 | 102.07,21.93 C18.1 | 102.07,21.93 | 97.62,21.93 102.07,21.93 | 97.62,21.93 97.63,21.93 C17.+ | 97.62,16.73 97.62,21.93 | 74.77,36.29 74.76,36.29 74.77,36.29 | 74.77,36.29 IC3.14 | 70.64,37.62 69.05,37.62 C12.1 | C12.1 | 67.14,35.71 67.15,35.71 | C12.1 67.14,35.71
VPP  (via drill 0.71)
  Top 0.406: R42.2 108.74,31.9 v110.01,33.17
  Bottom 0.406: v110.01,33.17 110.01,28.73 110.96,27.78 111.91,27.78 112.55,27.14 112.55,21.43 113.5,20.47 113.5,14.28 105.58,6.36 | 105.58,6.36 105.56,6.35 | 14.76,22.86 14.76,23.01 | 14.76,22.86 C2.1 | 14.76,19.84 14.76,22.86 | 14.76,19.84 R2.1 | 14.76,19.84 14.76,19.52 15.71,18.57 18.79,18.57 19.68,17.68 19.68,12.22 | 19.68,12.22 21.43,12.22 28.41,5.23 74.45,5.23 | 19.68,12.22 18.41,12.22 18.25,12.38 R5.1 | D1.C 10.47,31.9 10.47,31.87 13.17,29.17 | C2.1 14.76,27.62 13.19,29.19 | 13.19,29.19 C3.+ | 105.58,6.36 105.56,6.38 105.53,6.35 JP1.3 | 13.19,29.19 13.17,29.17 | C3.+ 13.17,29.17 | C2.1 | 74.45,5.23 74.51,5.23 75.53,4.22 84.61,4.22 JP1.3 | JP1.3 | T2.1 74.48,5.27 74.45,5.23
VUSB
  Bottom 0.406: C8.1 28.41,11.58 PIC1.18
WR
  Top 0.406: PIC1.8 41.75,38.25 43.02,39.52 49.37,39.52 50.32,38.57 50.32,36.67 49.37,35.71 PIC2.9

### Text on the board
Top: Mecséry I. 2007.06.30. ICD2 potyo2-rev1. | parts
Bottom: sold
tPlace: PGM | PGC | PGD | Vss | Vdd | Vpp | 1
_tplace: 1 | 1 | 6 | 6 | 1 | 1 | 2 | 2 | 3 | 3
